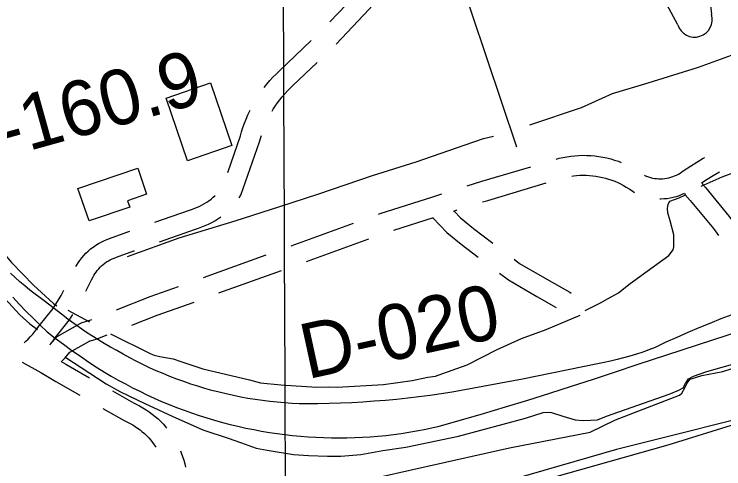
# Model space of a CAD drawing. Extents: x 3419139 to 3457078, y 540382 to 565875.
# Drawn here: x 3438619 to 3439688, y 562061 to 562745 of the extents above; entities that cross this region are included whole.
import ezdxf

# ---------------------------------------------------------------- set-up
doc = ezdxf.new("R2010")
doc.units = 0
for name, color, linetype in [('V-BLDG-OTLN', 7, 'Continuous'), ('V-GRID-MAJR', 7, 'Continuous'), ('V-RAIL-TRAK', 7, 'Continuous'), ('V-RIVR-RANG-IDEN', 7, 'Continuous'), ('V-ROAD-CNTR', 7, 'Continuous'), ('V-SITE-OTLN', 7, 'Continuous'), ('V-SITE-VEGE', 7, 'Continuous'), ('V-TOPO-SHOR', 7, 'Continuous'), ('V-TOPO-WATR-IDEN', 7, 'Continuous'), ('V-UTIL-LINE', 7, 'Continuous')]:
    doc.layers.add(name, color=color, linetype=linetype)

msp = doc.modelspace()

# ---------------------------------------------------------------- linework, layer by layer
at = {"layer": 'V-BLDG-OTLN'}
for points in [[(3438880.366, 562524.009), (3438848.036, 562618.31), (3438914.805, 562641.2000000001), (3438947.137, 562546.902)], [(3438793.3710000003, 562454.547), (3438732.111, 562433.67), (3438715.457, 562482.544), (3438805.4560000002, 562513.214), (3438818.881, 562473.817), (3438790.1410000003, 562464.024)]]:
    msp.add_lwpolyline(points, close=True, dxfattribs=at)
at = {"layer": 'V-GRID-MAJR'}
msp.add_spline([(3439098.765, 545841.133), (3439072.333, 551898.653), (3439045.886, 557959.642), (3439019.4390000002, 564020.648), (3439019.424, 564024.098)], degree=3, dxfattribs=at)
at = {"layer": 'V-RAIL-TRAK'}
for points in [[(3439700.031, 562292.5650000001), (3439683.315, 562286.081), (3439666.667, 562279.419), (3439650.09, 562272.574), (3439633.589, 562265.554), (3439617.162, 562258.353), (3439600.8170000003, 562250.976), (3439584.552, 562243.425), (3439575.193, 562239.7980000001), (3439565.751, 562236.382), (3439556.234, 562233.183), (3439546.648, 562230.201), (3439536.9960000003, 562227.437), (3439527.284, 562224.893), (3439517.517, 562222.571), (3439507.699, 562220.469), (3439497.836, 562218.593), (3439385.026, 562195.31), (3439279.111, 562176.099), (3439262.373, 562173.513), (3439245.6040000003, 562171.127), (3439228.806, 562168.946), (3439211.986, 562166.965), (3439195.1410000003, 562165.1900000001), (3439178.276, 562163.6190000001), (3439161.394, 562162.251), (3439144.4960000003, 562161.087), (3439127.588, 562160.129), (3439110.665, 562159.373), (3439093.737, 562158.824), (3439076.804, 562158.48), (3439059.867, 562158.339), (3439048.754, 562158.652), (3439037.648, 562159.175), (3439026.554, 562159.906), (3439015.4760000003, 562160.846), (3439004.419, 562161.997), (3438993.3850000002, 562163.355), (3438982.377, 562164.921), (3438971.401, 562166.6950000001), (3438960.461, 562168.675), (3438949.562, 562170.865), (3438938.703, 562173.257), (3438927.894, 562175.854), (3438917.133, 562178.655), (3438906.429, 562181.66), (3438895.7830000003, 562184.865), (3438885.199, 562188.2710000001), (3438874.683, 562191.875), (3438864.236, 562195.678), (3438853.861, 562199.68), (3438843.565, 562203.8740000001), (3438833.35, 562208.261), (3438823.218, 562212.843), (3438813.177, 562217.6140000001), (3438803.228, 562222.5750000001), (3438793.373, 562227.721), (3438783.616, 562233.054), (3438773.964, 562238.569), (3438764.349, 562243.853), (3438754.838, 562249.326), (3438745.4390000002, 562254.984), (3438736.1520000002, 562260.829), (3438726.983, 562266.854), (3438717.935, 562273.06), (3438709.0100000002, 562279.443), (3438700.211, 562285.9990000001), (3438690.6550000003, 562293.4230000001), (3438666.612, 562312.105), (3438658.674, 562317.776), (3438650.855, 562323.613), (3438643.1580000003, 562329.607), (3438635.5870000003, 562335.761), (3438628.144, 562342.071), (3438620.835, 562348.535), (3438613.663, 562355.148)], [(3438617.196, 562318.704), (3438627.268, 562308.019), (3438637.4930000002, 562297.478), (3438647.867, 562287.087), (3438658.389, 562276.843), (3438669.055, 562266.752), (3438681.384, 562257.2980000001), (3438693.842, 562248.019), (3438706.431, 562238.911), (3438719.143, 562229.982), (3438731.982, 562221.233), (3438744.94, 562212.662), (3438755.245, 562206.301), (3438765.661, 562200.1240000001), (3438776.186, 562194.132), (3438786.813, 562188.326), (3438797.543, 562182.706), (3438808.3680000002, 562177.279), (3438819.286, 562172.04), (3438830.298, 562166.998), (3438841.394, 562162.1460000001), (3438852.576, 562157.495), (3438863.838, 562153.039), (3438875.176, 562148.783), (3438886.588, 562144.728), (3438898.069, 562140.8740000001), (3438909.615, 562137.2220000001), (3438921.225, 562133.775), (3438932.895, 562130.533), (3438944.6180000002, 562127.498), (3438956.394, 562124.67), (3438968.217, 562122.049), (3438980.085, 562119.636), (3438991.992, 562117.432), (3439003.94, 562115.4400000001), (3439015.507, 562113.703), (3439027.107, 562112.169), (3439038.7290000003, 562110.84), (3439050.3740000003, 562109.718), (3439062.038, 562108.8), (3439073.713, 562108.087), (3439085.401, 562107.583), (3439097.097, 562107.284), (3439108.796, 562107.192), (3439120.494, 562107.307), (3439132.188, 562107.629), (3439143.876, 562108.155), (3439155.551, 562108.888), (3439167.213, 562109.828), (3439178.8540000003, 562110.975), (3439190.4760000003, 562112.3250000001), (3439202.0700000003, 562113.879), (3439213.6350000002, 562115.64), (3439225.167, 562117.604), (3439236.665, 562119.7710000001), (3439248.1210000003, 562122.1410000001), (3439259.532, 562124.713), (3439292.882, 562134.261), (3439326.176, 562143.9990000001), (3439359.413, 562153.928), (3439392.593, 562164.049), (3439425.715, 562174.361), (3439458.776, 562184.861), (3439491.778, 562195.553), (3439524.716, 562206.434), (3439557.59, 562217.504), (3439715.927, 562269.332)]]:
    msp.add_lwpolyline(points, dxfattribs=at)
at = {"layer": 'V-ROAD-CNTR'}
for p, q in [((3439036.3311361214, 562396.1851298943), (3439130.356950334, 562430.2271962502)), ((3439059.5149119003, 562372.6731423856), (3439153.5407160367, 562406.7152050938)), ((3438904.6178324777, 562348.7353145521), (3438998.70405641, 562382.6136989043)), ((3438927.809961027, 562325.2007052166), (3439021.896184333, 562359.0790893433))]:
    msp.add_line(p, q, dxfattribs=at)
for points in [[(3439094.680506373, 562733.2292538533), (3439131.815035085, 562772.3425885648), (3439138.6146879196, 562780.1898123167), (3439145.3958723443, 562788.3153487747), (3439152.022792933, 562796.567832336), (3439158.492521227, 562804.9428284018), (3439160.837472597, 562808.0988672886)], [(3439104.2645109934, 562699.7524949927), (3439154.040964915, 562752.1814114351), (3439161.4693120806, 562760.7541876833), (3439168.6101276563, 562769.3106512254), (3439171.8762318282, 562773.3779205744)], [(3438995.7324789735, 562634.3330945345), (3438999.8816751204, 562639.5348673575), (3439004.320488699, 562644.7293386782), (3439008.933215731, 562649.7648449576), (3439013.714718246, 562654.6414587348), (3439018.4707611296, 562659.1719144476), (3439066.4296735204, 562704.9292891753)], [(3439007.865009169, 562598.8339215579), (3439009.4922264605, 562601.5689564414), (3439012.6325983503, 562606.4569416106), (3439015.93311306, 562611.2331318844), (3439019.3969638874, 562615.8910972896), (3439023.01832488, 562620.4311326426), (3439026.7915113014, 562624.8466613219), (3439030.7107842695, 562629.1251550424), (3439034.777281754, 562633.2725412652), (3439039.171238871, 562637.4580855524), (3439075.4208937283, 562672.0437122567)], [(3438940.9340451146, 562506.3624866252), (3438960.317801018, 562561.7400883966), (3438961.8903696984, 562567.5599284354), (3438963.896774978, 562574.0883128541), (3438966.1235701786, 562580.5438569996), (3438968.5699895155, 562586.9198982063), (3438971.2327090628, 562593.2103570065), (3438974.1059010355, 562599.4042584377), (3438974.626593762, 562600.432868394)], [(3438958.0852646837, 562468.3672212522), (3438960.8196540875, 562472.3678369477), (3438988.994198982, 562552.8599116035), (3438990.7176303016, 562559.2380715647), (3438991.6773042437, 562562.3606313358)], [(3439435.4021265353, 562526.7002388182), (3439439.8648753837, 562527.8920532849), (3439445.7635515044, 562529.218618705), (3439451.703858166, 562530.3170776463), (3439457.6877587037, 562531.1841009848), (3439463.70239351, 562531.8163462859), (3439469.7337552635, 562532.2137144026), (3439475.7783992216, 562532.3765144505), (3439481.8243336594, 562532.3012446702), (3439487.860751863, 562531.9935577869), (3439493.8861108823, 562531.4486172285), (3439499.881029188, 562530.6692224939), (3439505.8390950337, 562529.6577677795), (3439511.7545451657, 562528.4160212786), (3439517.6193261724, 562526.9442890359), (3439523.4257213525, 562525.2425864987), (3439529.153686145, 562523.3162997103), (3439533.5388542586, 562521.652752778)], [(3439568.486438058, 562502.4302435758), (3439569.763803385, 562501.4879868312), (3439571.356090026, 562500.819446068), (3439574.28141401, 562499.775590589), (3439577.267190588, 562498.8924401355), (3439580.297098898, 562498.1723913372), (3439583.3580871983, 562497.619657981), (3439586.447330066, 562497.2358765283), (3439589.556718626, 562497.0203429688), (3439592.66437841, 562496.9745026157), (3439595.7720023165, 562497.1010216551), (3439598.8768618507, 562497.3967603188), (3439601.9567904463, 562497.8600563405), (3439605.002232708, 562498.4901751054), (3439608.0133585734, 562499.2882857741), (3439610.9768559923, 562500.2481358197), (3439613.8770854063, 562501.3669538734), (3439616.715112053, 562502.6443032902), (3439619.4803389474, 562504.0751934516), (3439622.1590919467, 562505.653024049), (3439624.7516593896, 562507.3779719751), (3439627.96070178, 562509.7750757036), (3439637.6893732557, 562516.111081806), (3439647.2498939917, 562522.0756316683), (3439656.9211436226, 562527.8576580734), (3439659.083278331, 562529.0951733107)], [(3439301.3902961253, 562486.2362807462), (3439323.6072708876, 562493.2771714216), (3439397.143687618, 562515.0531583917)], [(3439459.1647636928, 562501.0848355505), (3439461.408241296, 562501.4098990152), (3439466.25760649, 562501.9196537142), (3439471.124244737, 562502.2402855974), (3439475.9956007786, 562502.3714855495), (3439480.873666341, 562502.3107553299), (3439485.745248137, 562502.0624422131), (3439490.5998891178, 562501.6233827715), (3439495.434970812, 562500.9947775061), (3439500.2449049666, 562500.1782322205), (3439505.0194548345, 562499.1759787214), (3439509.7466738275, 562497.9897109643), (3439514.4222786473, 562496.6194135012), (3439519.048313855, 562495.0637002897), (3439523.6087848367, 562493.3336508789), (3439528.092710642, 562491.4262427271), (3439532.502919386, 562489.3439667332), (3439536.830167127, 562487.0919040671), (3439541.066224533, 562484.6733412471), (3439545.2031407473, 562482.0930122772), (3439549.236108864, 562479.3513798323), (3439553.3214992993, 562476.3377653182)], [(3439654.0675928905, 562490.9694891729), (3439662.8881060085, 562496.4723683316), (3439672.0708563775, 562501.9623419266), (3439681.352126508, 562507.2745517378), (3439681.4415705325, 562507.3235064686)], [(3439324.76095728, 562462.1723047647), (3439332.3987291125, 562464.5928285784), (3439420.600019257, 562490.7114542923)], [(3439654.759328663, 562491.4010443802), (3439655.722459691, 562488.7786940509), (3439660.14743956, 562483.795543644), (3439696.0411193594, 562440.4070446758), (3439709.1303964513, 562422.4234783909)], [(3438831.407234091, 562431.5936130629), (3438883.2733420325, 562449.8885462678), (3438887.76617537, 562451.2523707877), (3438891.56026717, 562452.5949350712), (3438895.294793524, 562454.1091406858), (3438898.9554972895, 562455.7871059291), (3438902.532258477, 562457.6285135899), (3438906.0251610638, 562459.630939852), (3438909.4281405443, 562461.791330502), (3438912.7293324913, 562464.0997664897), (3438915.9215284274, 562466.5547090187), (3438918.9988606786, 562469.1485338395), (3438921.954648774, 562471.8801782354), (3438921.983173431, 562471.9090222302)], [(3439167.967276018, 562443.8440227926), (3439170.3630037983, 562444.7113965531), (3439249.9563672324, 562469.9361015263), (3439263.2607746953, 562474.1524666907)], [(3439591.744706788, 562466.9848048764), (3439593.0536215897, 562466.9654973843), (3439597.8059976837, 562467.1589783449), (3439602.5331381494, 562467.6092396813), (3439607.231209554, 562468.3159436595), (3439611.889767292, 562469.2798248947), (3439616.4846414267, 562470.497714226), (3439621.005144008, 562471.9618641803), (3439625.4409145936, 562473.6730461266), (3439628.894209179, 562475.2273175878)], [(3439628.762023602, 562475.1678230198), (3439629.519540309, 562473.1053059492), (3439637.36656044, 562464.268456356), (3439672.3328806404, 562422.0009553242), (3439679.906185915, 562411.5958705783)], [(3439281.0168129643, 562448.3091329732), (3439286.6314465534, 562450.0884941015)], [(3439281.726114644, 562448.5339212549), (3439291.3281998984, 562438.3030077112), (3439310.841854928, 562422.4757730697), (3439340.3345827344, 562400.117625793)], [(3438838.120479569, 562402.1499837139), (3438892.6246579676, 562421.3754537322), (3438897.13182463, 562422.7436292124), (3438902.2057328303, 562424.5390649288), (3438907.1872064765, 562426.5588593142), (3438912.0785027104, 562428.8008940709), (3438916.865741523, 562431.2654864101), (3438921.5328389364, 562433.9410601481), (3438926.0718594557, 562436.8226694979), (3438930.345989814, 562439.8114555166)], [(3439191.305298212, 562419.8778917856), (3439250.9127382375, 562438.7686638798)], [(3439250.0149659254, 562438.4841421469), (3439270.8478001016, 562416.2869922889), (3439292.326145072, 562398.8662269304), (3439318.179991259, 562379.2666800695)], [(3438712.4920571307, 562364.9826519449), (3438713.2165422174, 562366.3225639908), (3438715.6859996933, 562370.3644742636), (3438718.355834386, 562374.2681958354), (3438721.226474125, 562378.0318702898), (3438724.28729729, 562381.6383288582), (3438727.529375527, 562385.0825137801), (3438730.9485139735, 562388.3568444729), (3438734.533271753, 562391.4496705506), (3438738.271406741, 562394.350463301), (3438742.150585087, 562397.0525034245), (3438746.1679816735, 562399.5548496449), (3438750.3105250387, 562401.8432370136), (3438754.5611005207, 562403.9153178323), (3438758.9186742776, 562405.765581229), (3438763.0257903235, 562407.2638995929), (3438789.269274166, 562416.7301271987), (3438793.685167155, 562418.2877622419)], [(3438727.2160892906, 562327.9971154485), (3438736.0754839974, 562345.1165702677), (3438737.718977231, 562348.5638504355), (3438739.229457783, 562351.3574360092), (3438740.8840003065, 562354.0655257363), (3438742.680165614, 562356.6918041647), (3438744.605525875, 562359.2161297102), (3438746.66070271, 562361.6376711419), (3438748.840624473, 562363.9534862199), (3438751.1354860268, 562366.1511555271), (3438753.540728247, 562368.2263294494), (3438756.0525932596, 562370.175536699), (3438758.665414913, 562371.9954965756), (3438761.3620183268, 562373.6751503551), (3438764.1454749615, 562375.2127629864), (3438767.0048994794, 562376.6066821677), (3438769.9293257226, 562377.848418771), (3438773.2562096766, 562379.0621004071), (3438799.3487258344, 562388.4738728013), (3438800.398412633, 562388.8441328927)], [(3439372.209889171, 562375.9532690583), (3439380.3156253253, 562369.8083900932), (3439421.1988519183, 562345.9833508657), (3439455.852012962, 562326.2706688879), (3439458.0332818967, 562324.7954016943)], [(3439350.0553224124, 562355.1023045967), (3439363.640374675, 562344.8036099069), (3439406.229148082, 562319.9846491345), (3439435.4794745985, 562303.3454056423)], [(3438634.2500588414, 562249.9762978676), (3438637.087505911, 562252.4896399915), (3438640.701348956, 562255.9483863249), (3438644.1779388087, 562259.5415199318), (3438647.515420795, 562263.2681655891), (3438650.708749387, 562267.1209762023), (3438653.7533209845, 562271.0930925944), (3438657.0902797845, 562275.8120765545), (3438678.3499607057, 562302.0628612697), (3438689.9458899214, 562321.2511514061), (3438694.179443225, 562329.4318597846)], [(3438773.415733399, 562299.9333502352), (3438824.2445336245, 562319.7946535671), (3438866.9833429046, 562335.1839608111)], [(3438796.480053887, 562276.7367629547), (3438834.7874663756, 562291.705346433), (3438890.1754717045, 562311.6493515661)], [(3438673.354055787, 562247.4310629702), (3438674.1712506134, 562248.4170237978), (3438677.9146790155, 562253.3009074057), (3438681.0197202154, 562257.6919234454), (3438702.9600392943, 562284.7831387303), (3438707.91889553, 562292.988774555)], [(3438673.7989889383, 562247.9310976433), (3438684.224605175, 562259.7990843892), (3438718.5687345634, 562279.4326423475), (3438721.58428231, 562280.9141560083), (3438733.1264196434, 562284.1903408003), (3438736.1613562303, 562285.3762392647)], [(3438690.309989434, 562221.6067469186), (3438695.9805022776, 562227.7253279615), (3438703.459394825, 562236.2389156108), (3438732.6412654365, 562252.9213576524), (3438732.3817176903, 562252.7938439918), (3438742.7035803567, 562255.7236591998), (3438759.2256276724, 562262.1796328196)], [(3438631.5540645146, 562221.0617698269), (3438659.6605053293, 562205.6639924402), (3438682.2412231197, 562192.0574584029), (3438718.3444201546, 562171.428170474)], [(3438690.2701335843, 562222.2449426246), (3438697.4267768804, 562217.9325415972), (3438732.7606522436, 562197.742842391)], [(3438767.4972768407, 562177.9102385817), (3438798.9164486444, 562159.983385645), (3438803.211425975, 562157.9979275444), (3438808.2709495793, 562155.4030698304), (3438813.2227929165, 562152.5963888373), (3438818.0472151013, 562149.5913604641), (3438822.7456321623, 562146.3917698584), (3438827.3140768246, 562142.9946348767), (3438831.7350216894, 562139.412299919), (3438836.0011431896, 562135.6534888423), (3438840.110338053, 562131.7193443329), (3438844.0504876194, 562127.6232492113), (3438847.823167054, 562123.3634103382), (3438849.220273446, 562121.6470526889)], [(3438753.0812231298, 562151.5958447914), (3438785.1635513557, 562133.2906143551), (3438790.0665740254, 562131.0240724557), (3438794.023050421, 562128.9949301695), (3438797.8892070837, 562126.8036111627), (3438801.666784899, 562124.4506395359), (3438805.344367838, 562121.9462301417), (3438808.911923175, 562119.2933651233), (3438812.3669783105, 562116.4937000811), (3438815.7028568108, 562113.5545111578), (3438818.9176619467, 562110.4766556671), (3438822.001512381, 562107.2707507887), (3438824.950832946, 562103.9405896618), (3438827.7574484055, 562100.4926375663), (3438830.419572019, 562096.9317290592), (3438832.843459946, 562093.3936141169)], [(3438869.7973343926, 562087.5168517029), (3438871.0595616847, 562084.4803676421), (3438873.024214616, 562079.1440516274), (3438874.767801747, 562073.7291638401), (3438876.2844040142, 562068.246495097), (3438877.503406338, 562063.009771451)]]:
    msp.add_lwpolyline(points, dxfattribs=at)
at = {"layer": 'V-SITE-OTLN'}
for p, q in [((3440448.841, 562357.8), (3439603.4960000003, 562096.17)), ((3439603.4960000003, 562096.17), (3438970.994, 561918.5430000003))]:
    msp.add_line(p, q, dxfattribs=at)
at = {"layer": 'V-SITE-VEGE'}
for points in [[(3439150.4760000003, 562043.995), (3439235.073, 562063.343), (3439365.054, 562091.996), (3439486.7600000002, 562115.9), (3439524.65, 562134.189), (3439621.039, 562171.307), (3439624.4960000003, 562174.719), (3439629.258, 562182.598), (3439632.5670000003, 562189.532), (3439637.005, 562195.465), (3439654.889, 562201.296), (3439686.518, 562207.264), (3439764.969, 562232.145)], [(3439782.983, 562153.737), (3439526.411, 562089.539), (3439288.352, 562021.094)]]:
    msp.add_lwpolyline(points, dxfattribs=at)
at = {"layer": 'V-TOPO-SHOR'}
msp.add_line((3438700.132, 562299.446), (3438733.026, 562282.026), dxfattribs=at)
for points in [[(3439395.5810000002, 562578.122), (3439473.671, 562604.15), (3439520.2060000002, 562625.482), (3439573.921, 562641.608), (3439650.023, 562665.1410000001), (3439721.535, 562690.975), (3439748.339, 562701.377), (3439765.21, 562707.977)], [(3439653.949, 562485.818), (3439685.367, 562500.099), (3439743.927, 562521.349), (3439814.895, 562548.01), (3439897.91, 562577.683), (3439983.349, 562609.745), (3440040.537, 562631.345), (3440051.238, 562638.4890000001), (3440054.714, 562643.963), (3440055.449, 562651.174), (3440053.88, 562673.176)], [(3438790.051, 562380.31), (3438867.9, 562407.953), (3438951.919, 562433.84), (3439019.417, 562455.371), (3439078.305, 562474.21), (3439158.904, 562502.182), (3439224.676, 562522.6950000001), (3439298.383, 562547.963), (3439326.2830000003, 562557.738), (3439341.2800000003, 562561.345)], [(3438530.645, 562479.1190000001), (3438576.606, 562416.2660000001), (3438615.471, 562371.329), (3438648.569, 562337.084), (3438678.619, 562309.389), (3438683.668, 562305.748)], [(3439479.191, 562298.77), (3439502.292, 562310.295), (3439514.021, 562317.088), (3439529.543, 562325.573), (3439544.7490000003, 562338.182), (3439563.394, 562351.457), (3439605.182, 562381.753), (3439611.4220000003, 562389.958), (3439612.483, 562394.4180000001), (3439612.608, 562412.629), (3439606.9080000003, 562433.629), (3439603.558, 562446.024), (3439603.259, 562452.553), (3439604.3340000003, 562459.076), (3439606.767, 562463.182), (3439620.5500000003, 562468.587), (3439629.164, 562472.269)], [(3438591.71, 562330.08), (3438610.781, 562310.747), (3438627.798, 562292.1140000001), (3438642.798, 562278.983), (3438654.537, 562270.182)], [(3438764.541, 562263.93), (3438825.174, 562233.822), (3438830.315, 562231.725), (3438838.892, 562229.605), (3438858.796, 562226.034), (3438870.109, 562222.175), (3438903.369, 562211.296), (3438973.6950000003, 562194.322), (3438990.503, 562190.085), (3439021.065, 562187.128), (3439075.3310000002, 562183.321), (3439092.862, 562184.232), (3439105.916, 562183.456), (3439175.356, 562187.447), (3439218.691, 562193.337), (3439242.092, 562198.332), (3439253.788, 562199.971), (3439263.434, 562203.684), (3439301.324, 562217.172), (3439346.497, 562240.228), (3439383.377, 562256.813), (3439420.5810000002, 562270.305), (3439471.5840000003, 562291.949)], [(3438695.526, 562229.323), (3438758.078, 562188.357), (3438779.258, 562176.552), (3438816.171, 562159.154), (3438857.186, 562139.674), (3438903.684, 562119.466), (3438943.37, 562106.166), (3438967.316, 562097.774), (3438983.732, 562091.488), (3439000.1720000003, 562088.633), (3439039.9050000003, 562082.1900000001), (3439062.525, 562080.665), (3439091.322, 562079.782), (3439111.21, 562079.645), (3439141.4020000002, 562082.182), (3439174.362, 562088.13), (3439209.373, 562093.377), (3439288.3540000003, 562109.984), (3439389.349, 562136.724), (3439416.1550000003, 562145.457), (3439425.074, 562146.084), (3439428.4990000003, 562145.373), (3439445.606, 562139.77), (3439464.085, 562134.158), (3439476.424, 562133.388), (3439497.6920000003, 562134.613), (3439511.4450000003, 562140.007), (3439605.6240000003, 562172.968), (3439620.069, 562179.04), (3439626.95, 562182.424), (3439630.423, 562189.258), (3439633.89, 562194.7220000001), (3439634.5870000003, 562196.088), (3439642.156, 562200.151), (3439662.091, 562206.873), (3439712.251, 562220.932)]]:
    msp.add_lwpolyline(points, dxfattribs=at)
at = {"layer": 'V-TOPO-WATR-IDEN'}
for points in [[(3439292.7786504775, 563933.6515597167), (3439441.002740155, 563666.5682475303), (3439578.9777109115, 563710.251211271), (3439771.7087161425, 563101.5000521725), (3439633.7337453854, 563057.8170884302), (3439669.2105617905, 562744.6712912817)], [(3439618.65867963, 562728.666533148), (3439464.250568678, 563015.282406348), (3439402.8518564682, 563209.2135134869), (3439254.76650928, 563162.329598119), (3439197.6986347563, 563342.5815234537), (3439345.783981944, 563389.4654388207), (3439277.9214667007, 563603.8128125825), (3439242.2267683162, 563917.6468015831)]]:
    msp.add_lwpolyline(points, dxfattribs=at)
msp.add_arc((3439643.934620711, 562736.6689122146), 26.51247382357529, 197.5678203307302, 17.5678203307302, dxfattribs=at)
at = {"layer": 'V-UTIL-LINE'}
msp.add_lwpolyline([(3438875.831639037, 564023.471937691), (3438965.075, 563761.866), (3439044.654, 563528.1190000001), (3439161.276, 563178.554), (3439262.432, 562881.373), (3439285.366, 562814.49), (3439375.705, 562544.899)], dxfattribs=at)

# ---------------------------------------------------------------- texts
at = {"layer": 'V-RIVR-RANG-IDEN'}
for s, height, rotation, p in [('R-160.9', 82.99999800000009, 15.566866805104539, (3438528.0774255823, 562507.2190714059)), ('D-020', 83, 12.291325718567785, (3439060.723694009, 562195.2632575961))]:
    msp.add_text(s, height=height, rotation=rotation, dxfattribs=at).set_placement(p)

doc.saveas('drawing.dxf')
